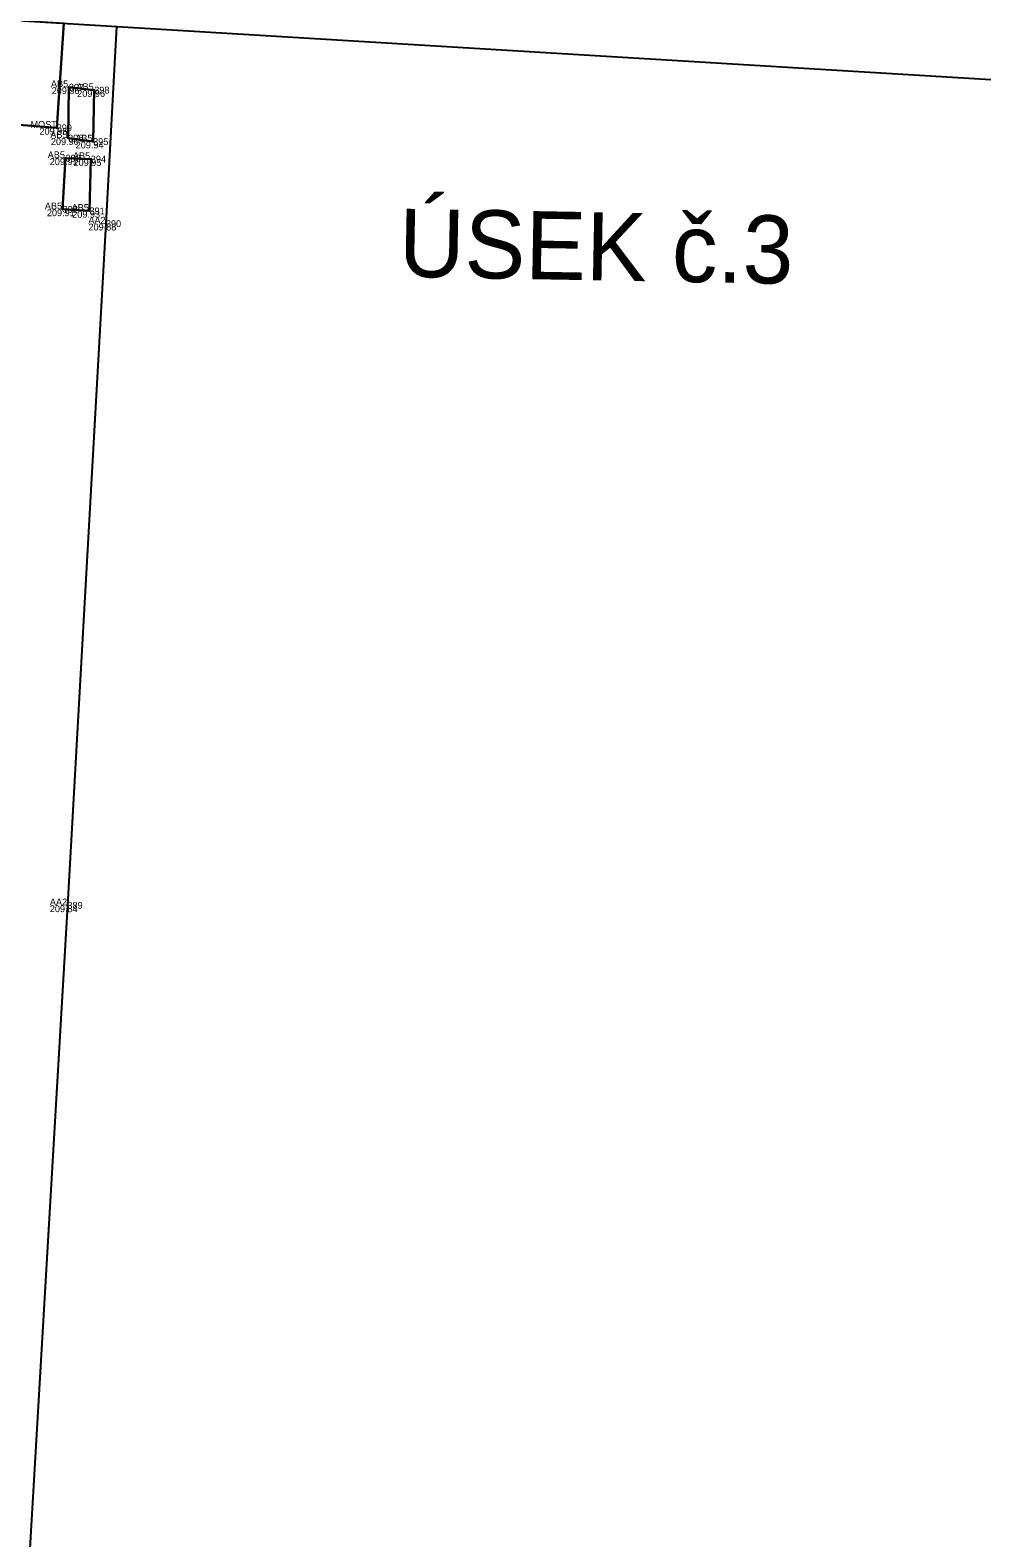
# Model space of a CAD drawing. Extents: x -263091 to -262565, y -1238731 to -1237092.
# Drawn here: x -262819.29 to -262791.06, y -1237979.18 to -1237934.9 of the extents above; entities that cross this region are included whole.
import ezdxf

# ---------------------------------------------------------------- set-up
doc = ezdxf.new("R2010")
doc.units = 0
for name, color, linetype in [('03_Asfalt', 7, 'Continuous'), ('04_Most', 7, 'Continuous'), ('08_Mimo_zelene', 7, 'Continuous'), ('10', 7, 'Continuous'), ('Groma (21)', 7, 'Continuous'), ('Groma (22)', 7, 'Continuous'), ('Groma (23)', 7, 'Continuous'), ('Groma (24)', 7, 'Continuous'), ('U003_Asfalt', 7, 'Continuous'), ('U003_Ostatné_plochy', 7, 'Continuous')]:
    doc.layers.add(name, color=color, linetype=linetype)

msp = doc.modelspace()

# ---------------------------------------------------------------- linework, layer by layer
at = {"layer": '03_Asfalt'}
msp.add_lwpolyline([(-262816.76, -1237934.791), (-262817.067, -1237940.584), (-262818.198, -1237960.603), (-262819.351, -1237980.318), (-262820.259, -1237997.242), (-262821.106, -1238014.516), (-262822.726, -1238037.787), (-262824.929, -1238056.475), (-262826.695, -1238065.295), (-262832.135, -1238081.046), (-262834.142, -1238085.994), (-262836.111, -1238090.171)], dxfattribs=at)
at = {"layer": '04_Most'}
msp.add_lwpolyline([(-262837.476, -1237933.537), (-262837.588, -1237934.475), (-262836.324, -1237934.594), (-262836.292, -1237935.17), (-262835.062, -1237935.275), (-262834.664, -1237935.731), (-262834.562, -1237935.803), (-262833.682, -1237935.77), (-262833.657, -1237935.467), (-262832.64, -1237935.62), (-262822.231, -1237936.276), (-262821.226, -1237936.393), (-262821.088, -1237936.694), (-262819.91, -1237936.875), (-262819.871, -1237937.657), (-262818.511, -1237937.77), (-262818.304, -1237934.697)], dxfattribs=at)
at = {"layer": '08_Mimo_zelene'}
for points in [[(-262818.157, -1237936.578), (-262817.409, -1237936.662), (-262817.443, -1237938.174), (-262818.177, -1237938.072)], [(-262818.253, -1237938.662), (-262817.511, -1237938.69), (-262817.55, -1237940.21), (-262818.337, -1237940.164)]]:
    msp.add_lwpolyline(points, close=True, dxfattribs=at)
at = {"layer": '10'}
msp.add_line((-262851.323, -1237932.698), (-262791.061, -1237936.346), dxfattribs=at)
at = {"layer": 'Groma (21)'}
for centre in [(-262818.157, -1237936.578), (-262817.409, -1237936.662), (-262818.511, -1237937.77), (-262818.177, -1237938.072), (-262817.443, -1237938.174), (-262818.253, -1237938.662), (-262817.511, -1237938.69), (-262818.337, -1237940.164), (-262817.55, -1237940.21), (-262817.067, -1237940.584), (-262818.198, -1237960.603)]:
    msp.add_circle(centre, 0.01, dxfattribs=at)
at = {"layer": 'U003_Asfalt'}
for points in [[(-262836.86, -1238089.78), (-262834.59, -1238083.86), (-262830.57, -1238069.55), (-262827.77, -1238056.55), (-262825.82, -1238041.97), (-262824.58, -1238026.07), (-262823.31, -1238002.11), (-262821.84, -1237980.92), (-262820.79, -1237960.68), (-262819.76, -1237938.03), (-262819.87, -1237937.66), (-262818.51, -1237937.77), (-262818.3, -1237934.7)], [(-262816.76, -1237934.79), (-262817.07, -1237940.58), (-262818.2, -1237960.6), (-262819.35, -1237980.32), (-262820.26, -1237997.24), (-262821.11, -1238014.52), (-262822.73, -1238037.79), (-262824.93, -1238056.48), (-262826.7, -1238065.3), (-262832.14, -1238081.05), (-262834.14, -1238085.99), (-262836.11, -1238090.17), (-262836.86, -1238089.78)], [(-262824.58, -1238026.07), (-262823.31, -1238002.11), (-262821.84, -1237980.92), (-262820.79, -1237960.68), (-262819.76, -1237938.03), (-262819.87, -1237937.66), (-262818.51, -1237937.77), (-262818.3, -1237934.7)], [(-262816.76, -1237934.79), (-262817.07, -1237940.58), (-262818.2, -1237960.6), (-262819.35, -1237980.32), (-262820.26, -1237997.24), (-262821.11, -1238014.52), (-262822.73, -1238037.79)]]:
    msp.add_lwpolyline(points, dxfattribs=at)
for points in [[(-262817.44, -1237938.17), (-262817.41, -1237936.66), (-262818.16, -1237936.58), (-262818.18, -1237938.07)], [(-262818.34, -1237940.16), (-262817.55, -1237940.21), (-262817.51, -1237938.69), (-262818.25, -1237938.66)]]:
    msp.add_lwpolyline(points, close=True, dxfattribs=at)
at = {"layer": 'U003_Ostatné_plochy'}
for points in [[(-262818.3, -1237934.7), (-262818.51, -1237937.77), (-262819.87, -1237937.66), (-262819.91, -1237936.88), (-262821.09, -1237936.69), (-262821.23, -1237936.39), (-262822.23, -1237936.28), (-262822, -1237934.47)], [(-262818.16, -1237936.58), (-262817.41, -1237936.66), (-262817.44, -1237938.17), (-262818.18, -1237938.07)], [(-262817.51, -1237938.69), (-262817.55, -1237940.21), (-262818.34, -1237940.16), (-262818.25, -1237938.66)]]:
    msp.add_lwpolyline(points, close=True, dxfattribs=at)
msp.add_lwpolyline([(-262818.51, -1237937.77), (-262819.87, -1237937.66), (-262819.91, -1237936.88), (-262821.09, -1237936.69), (-262821.23, -1237936.39), (-262822.23, -1237936.28), (-262822, -1237934.47), (-262818.3, -1237934.7), (-262818.51, -1237937.77)], dxfattribs=at)

# ---------------------------------------------------------------- texts
at = {"layer": '10'}
msp.add_text('ÚSEK č.3', height=2, rotation=358.9528, dxfattribs=at).set_placement((-262808.472, -1237942.142))
at = {"layer": 'Groma (22)'}
for s, p in [('397', (-262818.157, -1237936.678)), ('398', (-262817.409, -1237936.762)), ('399', (-262818.511, -1237937.87)), ('396', (-262818.177, -1237938.172)), ('395', (-262817.443, -1237938.274)), ('393', (-262818.253, -1237938.762)), ('394', (-262817.511, -1237938.79)), ('392', (-262818.337, -1237940.264)), ('391', (-262817.55, -1237940.31)), ('390', (-262817.067, -1237940.684)), ('389', (-262818.198, -1237960.703))]:
    msp.add_text(s, height=0.2, dxfattribs=at).set_placement(p)
at = {"layer": 'Groma (23)'}
for s, p in [('209.96', (-262818.659, -1237936.778)), ('209.96', (-262817.911, -1237936.862)), ('209.95', (-262819.018, -1237937.97)), ('209.90', (-262818.683, -1237938.272)), ('209.94', (-262817.955, -1237938.374)), ('209.91', (-262818.717, -1237938.862)), ('209.95', (-262818.018, -1237938.89)), ('209.91', (-262818.801, -1237940.364)), ('209.93', (-262818.057, -1237940.41)), ('209.88', (-262817.579, -1237940.784)), ('209.84', (-262818.715, -1237960.803))]:
    msp.add_text(s, height=0.2, dxfattribs=at).set_placement(p)
at = {"layer": 'Groma (24)'}
for s, p in [('AB5', (-262818.681, -1237936.578)), ('AB5', (-262817.933, -1237936.662)), ('MOST', (-262819.283, -1237937.77)), ('AB5', (-262818.701, -1237938.072)), ('AB5', (-262817.967, -1237938.174)), ('AB5', (-262818.777, -1237938.662)), ('AB5', (-262818.035, -1237938.69)), ('AB5', (-262818.861, -1237940.164)), ('AB5', (-262818.074, -1237940.21)), ('AA2', (-262817.582, -1237940.584)), ('AA2', (-262818.713, -1237960.603))]:
    msp.add_text(s, height=0.2, dxfattribs=at).set_placement(p)

doc.saveas('drawing.dxf')
